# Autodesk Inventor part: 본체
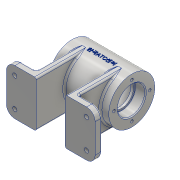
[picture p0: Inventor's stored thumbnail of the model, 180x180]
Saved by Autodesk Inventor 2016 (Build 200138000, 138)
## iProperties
Created: 2017-02
Part Number: 본체
Material: 알루미늄 6061
Document SubType Name: Modeling
Designer: CAMTIC
Density: 2.7 g/cm^3
Appearance: 알루미늄 - 평지
Mass: 354.768 g
Surface Area: 422.772 cm^2
Volume: 131.396 cm^3
Author: CAMTIC
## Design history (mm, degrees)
sketch "스케치1"
  geometry: L1 (52, 27)-(-52, 27); L2 (-52, 27)-(-52, -27); L3 (-52, -27)-(52, -27); L4 (52, -27)-(52, 27); L5 (52, 27)-(-52, -27); L6 (-52, 27)-(52, -27); 1 further point
  constraints: 12 end point, 2 midpoint, 2 parallel, 1 horizontal, 1 perpendicular
  dimensions: "d0" = 104 distance of L2.end L3.end; "d1" = 54 distance of L1.end L2.end
extrude "돌출1" new body sketch "스케치1" distance "d2" = 8; taper "d3" = 0 deg
sketch "스케치2"
  geometry: L1 (52, 0)-(52, 23.504) reference; L2 (35, -3.752)-(69, -3.752); L3 (69, -3.752)-(69, 27.256); L4 (69, 27.256)-(35, 27.256); L5 (35, 27.256)-(35, -3.752); L6 (35, -3.752)-(69, 27.256); L7 (69, -3.752)-(35, 27.256); 1 further point
  constraints: 14 end point, 3 midpoint, 2 parallel, 2 vertical, 1 horizontal, 1 perpendicular
  dimensions: "d5" = 17 distance between parallel lines of L1 L3
extrude "돌출2" cut sketch "스케치2" distance "d6" = 54; taper "d7" = 0 deg
node "작업 평면1"
sketch "스케치4"
  geometry: L1 (-35, 27)-(35, 27); L2 (35, 27)-(35, -27); L3 (35, -27)-(-35, -27); L4 (-35, -27)-(-35, 27); L5 (-35, 27)-(35, -27); L6 (35, 27)-(-35, -27); L7 (35, 0)-(-35, 0); 1 further point
  constraints: 14 end point, 4 midpoint, 2 parallel, 1 horizontal, 1 perpendicular
  dimensions: "d14" = 54 distance of L1.end L2.end; "d15" = 70 distance of L2.end L3.end
revolve "회전2" sketch "스케치4" stored, may be unused: angle "d16" = 90 deg
sketch "스케치5"
  geometry: L1 (-17, 27)-(-17, -27) reference; L2 (-17, -27)-(-25, -27); L3 (-25, -27)-(-25, 27); L4 (-25, 27)-(-17, 27); L5 (-17, 27)-(-17, -27); L6 (17, -27)-(17, 27) reference; L7 (17, -27)-(25, -27); L8 (25, -27)-(25, 27); L9 (25, 27)-(17, 27); L10 (17, 27)-(17, -27); 1 further point
  constraints: 16 end point, 4 parallel, 2 horizontal, 2 perpendicular
  dimensions: "d17" = 8 distance of L3.end L4.end; "d18" = 54 distance of L2.end L3.end; "d19" = 8 distance of L9.end L8.end; "d20" = 54 distance of L8.end L7.end
extrude "돌출3" join sketch "스케치5" stored distance "d21" = 0; taper "d22" = 0 deg
node "작업 평면2"
sketch "스케치6"
  geometry: L1 (0, 0)-(-5, 0); L2 (-5, 0)-(-5, 32); L3 (-5, 32)-(0, 32); L4 (0, 32)-(0, 0); L5 (27, -60)-(-27, -60) reference; C1 r 27 at (0, 0) reference; 1 further point
  constraints: 8 end point, 2 parallel, 1 coincident, 1 horizontal, 1 perpendicular
  dimensions: "d24" = 5 distance of L2.end L3.end; "d25" = 92 distance between parallel lines of L5 L3
revolve "회전3" sketch "스케치6" stored, may be unused: angle "d26" = 90 deg
node "작업 평면3"
sketch "스케치7"
  geometry: L1 (0, 0)-(-16.339, -25.16); L2 (0, 27)-(0, -27); A1 r 27 centre (0, 0) between (0, 27) and (0, -27) reference; 1 further point
  constraints: 4 end point, 2 point on circle
  dimensions: "d28" = 33 deg angle of L2 L1; "d29" = 30 distance of L1.start L1.end
node "작업 평면4"
sketch "스케치8"
  geometry: C1 r 6 at (0, 0); 1 further point
  constraints: 1 centre point
  dimensions: "d30" = 12 diameter of C1
extrude "돌출4" join sketch "스케치8" stored distance "d31" = 0; taper "d32" = 0 deg
sketch "스케치9"
  geometry: C1 r 16 at (0, 0); 1 further point
  constraints: 1 centre point
  dimensions: "d33" = 32 diameter of C1
extrude "돌출5" cut sketch "스케치9" distance "d34" = 12; taper "d35" = 0 deg
sketch "스케치10"
  geometry: C1 r 14 at (0, 0); 1 further point
  constraints: 1 centre point
  dimensions: "d36" = 28 diameter of C1
extrude "돌출6" cut sketch "스케치10" stored distance "d37" = 12; taper "d38" = 0 deg
sketch "스케치11"
  geometry: C1 r 14 at (0, 0) reference; C2 r 16 at (0, 0); 1 further point
  constraints: 1 centre point, 1 coincident
  dimensions: "d39" = 32 diameter of C2
extrude "돌출7" cut sketch "스케치11" distance "d40" = 12; taper "d41" = 0 deg
sketch "스케치12"
  geometry: C1 r 22 at (0, 0); 2 further points
  constraints: 1 centre point, 1 coincident
  dimensions: "d42" = 44 diameter of C1
extrude "돌출8" cut sketch "스케치12" distance "d43" = 20; taper "d45" = 0 deg; dims "d44" = 20, "d46" = 0
sketch "스케치13"
  geometry: C1 r 16 at (0, 0) reference; 2 further points
  dimensions: "d47" = 21 distance of point (0, 21) C1.centre
hole "구멍1" sketch "스케치13" at (0, 21) diameter "d48" = 3.242; stored, may be unused: countersink angle "d52" = 90 deg, drill point angle "d54" = 118 deg; dims "d49" = 8, "d50" = 4, "d51" = 2, "d53" = 10
sketch "스케치14"
  geometry: 2 further points
hole "구멍2" sketch "스케치14" at (0, 21) diameter "d58" = 3.242; stored, may be unused: countersink angle "d62" = 90 deg, drill point angle "d64" = 118 deg; dims "d59" = 8, "d60" = 4, "d61" = 2, "d63" = 10
sketch "스케치15"
  geometry: C1 r 5 at (0, 0) reference; 2 further points
  constraints: 1 coincident
hole "구멍3" sketch "스케치15" at (0, 0) diameter "d68" = 5.188; stored, may be unused: countersink angle "d72" = 90 deg, drill point angle "d74" = 118 deg; dims "d69" = 20, "d70" = 4, "d71" = 2, "d73" = 20
sketch "스케치16"
  geometry: C1 r 6 at (0, 0) reference; 2 further points
  constraints: 1 coincident
hole "구멍4" sketch "스케치16" at (0, 0) diameter "d75" = 5.188; stored, may be unused: countersink angle "d79" = 90 deg, drill point angle "d81" = 118 deg; dims "d76" = 20, "d77" = 4, "d78" = 2, "d80" = 20
sketch "스케치17" dims "d82" = 9
  geometry: L1 (-25, 27)-(-52, 27) reference; L2 (-52, 27)-(-52, -27) reference; L3 (-39.402, 21.5)-(-36.804, 17); L4 (-36.804, 17)-(-39.402, 12.5); L5 (-39.402, 12.5)-(-44.598, 12.5); L6 (-44.598, 12.5)-(-47.196, 17); L7 (-47.196, 17)-(-44.598, 21.5); L8 (-44.598, 21.5)-(-39.402, 21.5); 4 further points
  constraints: 12 end point, 1 coincident, 1 midpoint, 1 vertical alignment, 15 other
  dimensions: "d83" = 10 distance from line of L1 point (-42, 17); "d84" = 10 distance from line of L2 point (-42, 17)
extrude "돌출9" cut sketch "스케치17" distance "d85" = 3; taper "d86" = 0 deg
fillet "모깎기1" dims "d93" = 10
sketch "스케치19"
  geometry: C1 r 2.5 at (-42, 17); A1 r 10 centre (-42, 17) between (-42, 27) and (-52, 17) reference; 1 further point
  constraints: 1 centre point, 1 coincident
  dimensions: "d94" = 5 diameter of C1
extrude "돌출10" cut sketch "스케치19" stored distance "d95" = 3; taper "d96" = 0 deg
node "작업 평면5"
sketch "스케치20"
  geometry: L1 (-35, 87)-(35, 87) reference; L2 (-35, 33)-(-35, 87) reference; 2 further points
  constraints: 1 other
  dimensions: "d104" = 27 distance from line of L1 point (0, 60); "d105" = 35 distance from line of L2 point (0, 60)
feature "엠보싱1" sketch "스케치20" dims "d106" = 0.5, "d107" = 0
fillet "모깎기2" dims "d108" = 3
chamfer "모따기1" distance "d109" = 1; stored, may be unused: second distance "d110" = 2, angle "d111" = 45 deg
fillet "모깎기3" dims "d112" = 0.3
fillet "모깎기4" dims "d113" = 2
fillet "모깎기5" dims "d114" = 2
node "솔리드1"
pattern_circular "원형 패턴1" dims angle "d56" = 360 deg
pattern_circular "원형 패턴2" dims angle "d66" = 360 deg
pattern_linear "직사각형 패턴1" dims "d89" = 84, "d92" = 34
pattern_linear "직사각형 패턴2" dims "d99" = 84, "d102" = 34
other parameters: "d23" = -25, "d27" = -35
